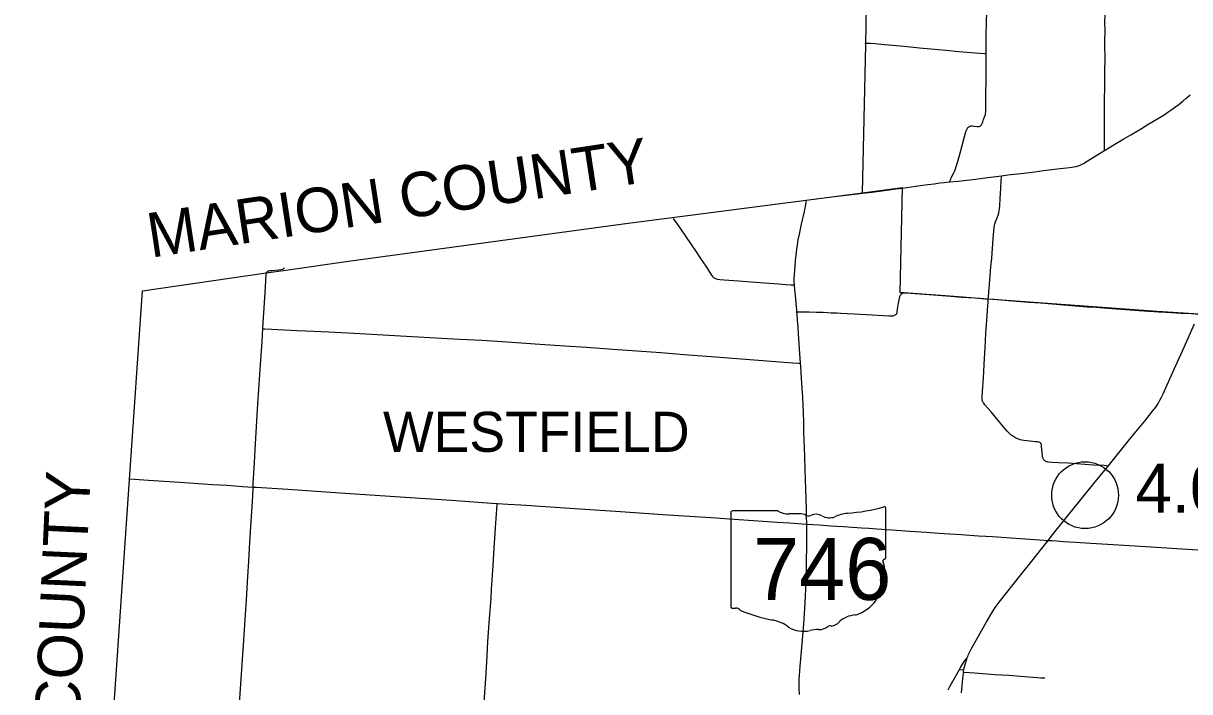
# Model space of a CAD drawing. Extents: x 9078 to 9739, y 4248 to 4966.
# Drawn here: x 9110.2 to 9241.2, y 4481.6 to 4556.7 of the extents above; entities that cross this region are included whole.
import ezdxf

# ---------------------------------------------------------------- set-up
doc = ezdxf.new("R2010")
doc.units = 0
for name, color, linetype in [('Default', 7, 'Continuous'), ('GM_X_Adjacent_County_Text', 7, 'Continuous'), ('GM_X_County', 7, 'Continuous'), ('GM_X_County_Road', 7, 'Continuous'), ('GM_X_State_Route', 7, 'Continuous'), ('GM_X_State_Shield', 7, 'Continuous'), ('GM_X_Township', 7, 'Continuous'), ('GM_X_Township_Road', 7, 'Continuous'), ('GM_X_Township_Text', 7, 'Continuous'), ('GM_X_US_Route', 7, 'Continuous')]:
    doc.layers.add(name, color=color, linetype=linetype)

msp = doc.modelspace()

# ---------------------------------------------------------------- linework, layer by layer
at = {"layer": 'Default'}
msp.add_circle((9229.48, 4503.7), 3.75, dxfattribs=at)
at = {"layer": 'GM_X_County'}
msp.add_lwpolyline([(9120.12, 4475.84), (9122.16, 4505.46), (9123.61, 4526.66), (9137.52, 4528.67), (9139.7, 4528.98), (9147, 4530.03), (9178.15, 4534.24), (9183.12, 4534.88), (9198.17, 4536.84), (9204.48, 4537.65), (9204.85, 4554.27), (9205.29, 4580.7)], dxfattribs=at)
at = {"layer": 'GM_X_County_Road'}
for points in [[(9231.68, 4542.43), (9233.01, 4543.23), (9233.85, 4543.73), (9234.63, 4544.19), (9235.62, 4544.78), (9235.83, 4544.9), (9236.46, 4545.29), (9237.15, 4545.72), (9238.35, 4546.43), (9238.77, 4546.7), (9239.1, 4546.93), (9239.52, 4547.23), (9240, 4547.59), (9240.47, 4547.97), (9240.85, 4548.28), (9240.98, 4548.39), (9241.27, 4548.67)], [(9220.1, 4539.58), (9220.82, 4539.67), (9221.56, 4539.76), (9222.61, 4539.88), (9223.84, 4540.03), (9224.81, 4540.15), (9226.36, 4540.35), (9227.74, 4540.52), (9228.23, 4540.59), (9228.47, 4540.63), (9228.71, 4540.69), (9228.94, 4540.77), (9229.09, 4540.83), (9229.31, 4540.95), (9229.73, 4541.2), (9231.6, 4542.38), (9231.68, 4542.43)], [(9214.29, 4538.88), (9215.21, 4538.98), (9217.16, 4539.2), (9218.55, 4539.38), (9220.1, 4539.58)], [(9204.5, 4537.63), (9205.57, 4537.75), (9206.34, 4537.85)], [(9206.34, 4537.85), (9206.38, 4537.85), (9208.24, 4538.1), (9208.96, 4538.2)], [(9208.96, 4538.2), (9210.43, 4538.4), (9211.24, 4538.51), (9211.81, 4538.58), (9212.54, 4538.68), (9213.18, 4538.77), (9213.67, 4538.83), (9213.92, 4538.85), (9214.29, 4538.88)], [(9198.21, 4536.84), (9198.72, 4536.91), (9200.75, 4537.16), (9203.91, 4537.56), (9204.5, 4537.63)], [(9183.2, 4534.77), (9183.31, 4534.65), (9183.46, 4534.45), (9183.7, 4534.12), (9184.53, 4532.9), (9185.31, 4531.75), (9185.73, 4531.14), (9186.37, 4530.19), (9186.88, 4529.44), (9187.54, 4528.41), (9187.64, 4528.27), (9187.69, 4528.21), (9187.75, 4528.16), (9187.82, 4528.11), (9187.89, 4528.07), (9187.96, 4528.03), (9188.04, 4528.01), (9188.2, 4527.97), (9188.44, 4527.94), (9188.93, 4527.89), (9190.57, 4527.78), (9192.45, 4527.63), (9194, 4527.52), (9195.06, 4527.43), (9195.88, 4527.37), (9196.45, 4527.32), (9196.69, 4527.31), (9196.83, 4527.31)], [(9137.14, 4522.41), (9137.18, 4523.07), (9137.39, 4526.43), (9137.51, 4528.49), (9137.52, 4528.58), (9137.53, 4528.65)], [(9137.53, 4528.65), (9137.54, 4528.71), (9137.57, 4528.76), (9137.6, 4528.8), (9137.64, 4528.83), (9137.69, 4528.86), (9137.76, 4528.89), (9137.84, 4528.91), (9137.94, 4528.93), (9138.17, 4528.95), (9138.9, 4529.02), (9139.14, 4529.05), (9139.3, 4529.08), (9139.38, 4529.1), (9139.45, 4529.13), (9139.5, 4529.17), (9139.55, 4529.22)], [(9197.12, 4524.28), (9197.22, 4524.29), (9197.37, 4524.3), (9197.53, 4524.31), (9197.86, 4524.3), (9198.51, 4524.29), (9199.33, 4524.27), (9200.07, 4524.24), (9200.97, 4524.2), (9201.63, 4524.18), (9202.04, 4524.16), (9202.78, 4524.12), (9203.6, 4524.06), (9205.56, 4523.94), (9206.79, 4523.87), (9207.45, 4523.83), (9207.69, 4523.83), (9207.86, 4523.85), (9207.94, 4523.86), (9208.01, 4523.88), (9208.09, 4523.92), (9208.16, 4523.95), (9208.23, 4524), (9208.3, 4524.05), (9208.34, 4524.11), (9208.37, 4524.17), (9208.38, 4524.27), (9208.43, 4524.6), (9208.53, 4525.25), (9208.62, 4525.81), (9208.66, 4525.97), (9208.69, 4526.05), (9208.69, 4526.05)], [(9208.69, 4526.05), (9208.72, 4526.12), (9208.77, 4526.19), (9208.82, 4526.25), (9208.88, 4526.31), (9208.95, 4526.35), (9209.02, 4526.39), (9209.1, 4526.41), (9209.18, 4526.43), (9209.34, 4526.43), (9209.92, 4526.39), (9210.9, 4526.31), (9211.96, 4526.23), (9214.42, 4526.05), (9215.65, 4525.96), (9217.12, 4525.85), (9218.27, 4525.77), (9218.61, 4525.75)], [(9218.61, 4525.75), (9219.25, 4525.7), (9220.88, 4525.57), (9223.18, 4525.39), (9224.48, 4525.29), (9227.1, 4525.08), (9229.72, 4524.87), (9230.7, 4524.8), (9231.6, 4524.73), (9232.5, 4524.67), (9234.55, 4524.53), (9235.53, 4524.46), (9236.59, 4524.38), (9237.25, 4524.35), (9237.74, 4524.31), (9238.56, 4524.24), (9239.77, 4524.18), (9240.23, 4524.15), (9240.85, 4524.13), (9241.43, 4524.11), (9241.84, 4524.08), (9242.16, 4524.05), (9242.27, 4524.03)], [(9136.04, 4504.61), (9136.05, 4504.64), (9136.06, 4505.05), (9136.18, 4507.35), (9136.26, 4508.82), (9136.57, 4513.98), (9136.9, 4518.89), (9137.04, 4520.94), (9137.14, 4522.41)], [(9122.18, 4505.54), (9124.29, 4505.38), (9127.81, 4505.16), (9131.49, 4504.92), (9133.13, 4504.81), (9134.84, 4504.69), (9136.04, 4504.61)], [(9134.13, 4474.93), (9134.14, 4475.01), (9134.26, 4476.72), (9134.53, 4480.82), (9134.76, 4484.17), (9134.95, 4486.87), (9135.17, 4490.31), (9135.28, 4491.95), (9135.41, 4493.92), (9135.45, 4494.57), (9135.55, 4496.29), (9135.67, 4498.42), (9135.82, 4500.71), (9136, 4503.58), (9136.04, 4504.61)], [(9136.04, 4504.61), (9136.4, 4504.59), (9139.92, 4504.36), (9145.81, 4503.96), (9153.67, 4503.44), (9157.19, 4503.2), (9158.82, 4503.09), (9162.83, 4502.82), (9163.47, 4502.78)], [(9163.47, 4502.78), (9164.63, 4502.7), (9166.11, 4502.6), (9173.31, 4502.14), (9177.32, 4501.88), (9182.07, 4501.55), (9188.04, 4501.15), (9189.51, 4501.06), (9191.15, 4500.94), (9194.91, 4500.68), (9196.3, 4500.59), (9198.1, 4500.46), (9198.23, 4500.45)], [(9215.37, 4484.12), (9215.5, 4484.34), (9215.96, 4485.12), (9216.02, 4485.21), (9216.1, 4485.29), (9216.23, 4485.42)], [(9214.09, 4481.84), (9214.33, 4482.28), (9215.37, 4484.12)], [(9215.37, 4484.12), (9215.45, 4484.11), (9215.77, 4484.08), (9215.86, 4484.07)]]:
    msp.add_lwpolyline(points, dxfattribs=at)
at = {"layer": 'GM_X_State_Route'}
msp.add_lwpolyline([(9197.4, 4481.31), (9197.37, 4482.05), (9197.36, 4482.62), (9197.36, 4483.03), (9197.39, 4483.44), (9197.47, 4484.5), (9197.59, 4485.73), (9197.71, 4487.04), (9197.82, 4488.34), (9197.89, 4489.24), (9197.99, 4490.96), (9198.08, 4492.35), (9198.12, 4493.17), (9198.18, 4494.48), (9198.2, 4495.46), (9198.21, 4496.53), (9198.22, 4497.76), (9198.23, 4499.4), (9198.23, 4500.38), (9198.23, 4500.45), (9198.21, 4501.36), (9198.19, 4502.18), (9198.15, 4503.33), (9198.12, 4504.4), (9198.09, 4505.46), (9198.05, 4506.53), (9198, 4508.08), (9197.97, 4508.98), (9197.91, 4510.79), (9197.88, 4511.85), (9197.85, 4513), (9197.77, 4514.72), (9197.71, 4515.7), (9197.63, 4516.85), (9197.54, 4518.16), (9197.52, 4518.53), (9197.41, 4520.12), (9197.29, 4521.84), (9197.24, 4522.57), (9197.19, 4523.31), (9197.14, 4524.04), (9197.12, 4524.28), (9197.1, 4524.53), (9197.04, 4525.19), (9196.98, 4525.76), (9196.87, 4526.82), (9196.83, 4527.31), (9196.83, 4527.35), (9196.82, 4527.64), (9196.82, 4528.05), (9196.84, 4528.46), (9196.87, 4528.95), (9196.97, 4530.01), (9197.1, 4531.32), (9197.17, 4531.81), (9197.26, 4532.37), (9197.39, 4533.02), (9197.63, 4534.14), (9197.95, 4535.58), (9198.14, 4536.54), (9198.21, 4536.84)], dxfattribs=at)
at = {"layer": 'GM_X_State_Shield'}
for p, q in [((9189.7, 4501.76), (9189.7, 4491.19)), ((9194.97, 4501.94), (9189.87, 4501.94)), ((9207.1, 4496.68), (9207.1, 4502.2)), ((9207.1, 4496.68), (9207.1, 4496.68))]:
    msp.add_line(p, q, dxfattribs=at)
for centre, major_axis, start_param, end_param in [((9189.9, 4501.78), (0.202, 0), 1.712693, 3.28349), ((9196.18, 4503.17), (1.96, 0), 4.042523, 4.731795), ((9196.83, 4496.01), (7.02, 0), 1.404758, 1.657858), ((9198.42, 4501.84), (0.564, 0), 3.836095, 5.185415), ((9199.25, 4500.62), (1.17, 0), 0.950623, 2.079405), ((9200.77, 4502.29), (1.41, 0), 4.081561, 5.145723), ((9203.26, 4498.71), (3.71, 0), 1.699011, 2.107814), ((9200.9, 4516.35), (18.45, 0), 4.814394, 5.042369), ((9206.91, 4502.23), (0.194, 0), 6.141152, 7.989035), ((9207.06, 4496.27), (0.3, 0), 1.883978, 3.671073), ((9205.15, 4495.57), (1.8, 0), 5.934695, 6.695948), ((9206.9, 4496.66), (0.207, 0), 5.05454, 6.418171), ((9207.8, 4494.36), (1.31, 0), 2.387724, 3.262537), ((9201.94, 4493.66), (4.62, 0), 5.101752, 6.440018), ((9189.9, 4491.17), (0.203, 0), 3.00124, 4.508301), ((9189.93, 4492.25), (1.55, 0), 4.665946, 4.897461), ((9190.25, 4490.58), (0.56, 0), 0.519207, 1.627899), ((9197.32, 4500.08), (13.33, 0), 4.195997, 4.488961), ((9193.34, 4486.45), (4.17, 0), 0.823519, 1.323587), ((9200.68, 4490.17), (1.49, 0), 4.937069, 5.64225), ((9203.88, 4488.23), (2.53, 0), 1.647645, 2.488434), ((9197.85, 4490.53), (2.65, 0), 4.026481, 4.996735), ((9199.38, 4486.88), (2.17, 0), 1.495662, 1.94098), ((9199.57, 4489.74), (1.41, 0), 4.691044, 5.507374), ((9200.85, 4488.72), (0.397, 0), 1.147584, 2.315152)]:
    msp.add_ellipse(centre, major_axis=major_axis, ratio=0.8, start_param=start_param, end_param=end_param, dxfattribs=at)
at = {"layer": 'GM_X_Township'}
msp.add_lwpolyline([(9204.48, 4537.65), (9208.95, 4538.24), (9208.67, 4526.47), (9209.13, 4526.47), (9213.78, 4526.12), (9218.61, 4525.77), (9237.59, 4524.37), (9242.26, 4524.06), (9243.8, 4523.9), (9245.68, 4523.76), (9281.77, 4520.95)], dxfattribs=at)
at = {"layer": 'GM_X_Township_Road'}
for points in [[(9218.36, 4553.27), (9218.36, 4553.33), (9218.37, 4554.15), (9218.39, 4555.29), (9218.41, 4556.85), (9218.44, 4557.92), (9218.47, 4558.98), (9218.49, 4559.8), (9218.5, 4560.01)], [(9231.68, 4542.43), (9231.67, 4542.85), (9231.66, 4544.32), (9231.66, 4545.38), (9231.66, 4546.04), (9231.68, 4548.5), (9231.69, 4549.07), (9231.71, 4550.96), (9231.72, 4553.09), (9231.71, 4554), (9231.71, 4554.65), (9231.72, 4555.88), (9231.71, 4556.79), (9231.72, 4557.61), (9231.74, 4559.25), (9231.75, 4559.92)], [(9204.74, 4554.45), (9205.38, 4554.46), (9205.9, 4554.42), (9206.96, 4554.33), (9209.18, 4554.12), (9210.9, 4553.96), (9213.03, 4553.76), (9213.85, 4553.69), (9215.32, 4553.55), (9217.12, 4553.38), (9218.19, 4553.29), (9218.36, 4553.27)], [(9214.29, 4538.88), (9214.34, 4539.03), (9214.39, 4539.18), (9214.45, 4539.33), (9214.74, 4539.92), (9214.84, 4540.14), (9214.94, 4540.37), (9215.02, 4540.6), (9215.16, 4541.07), (9215.38, 4541.86), (9215.63, 4542.81), (9215.86, 4543.69), (9216.05, 4544.4), (9216.09, 4544.56), (9216.15, 4544.71), (9216.19, 4544.79), (9216.23, 4544.86), (9216.27, 4544.93), (9216.32, 4544.99), (9216.38, 4545.04), (9216.45, 4545.09), (9216.52, 4545.13), (9216.6, 4545.15), (9216.68, 4545.17), (9216.76, 4545.18), (9216.84, 4545.18), (9217.01, 4545.16), (9217.33, 4545.12), (9217.42, 4545.11), (9217.5, 4545.11), (9217.58, 4545.12), (9217.66, 4545.15), (9217.73, 4545.18), (9217.79, 4545.23), (9217.85, 4545.29), (9217.89, 4545.36), (9217.93, 4545.43), (9217.98, 4545.59), (9218.09, 4545.9), (9218.2, 4546.21), (9218.28, 4546.44), (9218.31, 4546.6), (9218.33, 4546.77), (9218.34, 4547.18), (9218.35, 4547.75), (9218.35, 4548.49), (9218.36, 4550.62), (9218.36, 4551.6), (9218.36, 4552.26), (9218.36, 4553.27)], [(9218.61, 4525.75), (9218.63, 4525.91), (9218.63, 4525.99), (9218.79, 4527.87), (9218.91, 4529.35), (9218.99, 4530.33), (9219.16, 4532.54), (9219.22, 4533.35), (9219.26, 4533.76), (9219.3, 4534.01), (9219.34, 4534.16), (9219.42, 4534.4), (9219.6, 4534.86), (9219.71, 4535.16), (9219.79, 4535.4), (9219.84, 4535.64), (9219.87, 4535.88), (9219.9, 4536.21), (9219.95, 4537.03), (9220.02, 4538.16), (9220.07, 4539.03), (9220.09, 4539.43), (9220.1, 4539.58)], [(9218.1, 4514.03), (9218.08, 4514.06), (9218.03, 4514.13), (9217.99, 4514.2), (9217.96, 4514.27), (9217.94, 4514.35), (9217.92, 4514.43), (9217.92, 4514.51), (9217.92, 4514.6), (9217.93, 4514.84), (9217.99, 4515.83), (9218.06, 4516.89), (9218.19, 4519.1), (9218.25, 4520.25), (9218.35, 4521.89), (9218.48, 4523.86), (9218.56, 4525), (9218.58, 4525.3), (9218.61, 4525.75)], [(9137.14, 4522.41), (9137.28, 4522.4), (9137.37, 4522.39), (9139.58, 4522.28), (9140.97, 4522.21), (9142.86, 4522.11), (9144.5, 4522.03), (9146.71, 4521.92), (9148.68, 4521.82), (9153.26, 4521.56), (9157.2, 4521.35), (9159.25, 4521.24), (9161.71, 4521.1), (9164.57, 4520.93), (9168.26, 4520.68), (9171.04, 4520.49), (9173.5, 4520.32), (9176.44, 4520.1), (9181.85, 4519.71), (9184.47, 4519.51), (9185.94, 4519.4), (9188.48, 4519.21), (9190.36, 4519.06), (9196.66, 4518.58), (9197.31, 4518.54), (9197.52, 4518.53)], [(9232.07, 4506.96), (9231.88, 4506.99), (9231.8, 4507.01), (9231.64, 4507.02), (9230.41, 4507.09), (9229.02, 4507.18), (9227.54, 4507.28), (9226.48, 4507.34), (9225.74, 4507.38), (9225.33, 4507.42), (9225.25, 4507.43), (9225.17, 4507.45), (9225.09, 4507.48), (9225.02, 4507.52), (9224.95, 4507.57), (9224.89, 4507.62), (9224.84, 4507.68), (9224.8, 4507.75), (9224.76, 4507.83), (9224.74, 4507.91), (9224.71, 4508.07), (9224.62, 4508.88), (9224.6, 4509.12), (9224.58, 4509.38), (9224.56, 4509.45), (9224.52, 4509.53), (9224.46, 4509.58), (9224.39, 4509.62), (9224.32, 4509.65), (9224.15, 4509.68), (9223.91, 4509.7), (9223.26, 4509.77), (9222.6, 4509.84), (9222.36, 4509.88), (9222.2, 4509.92), (9222.04, 4509.98), (9221.89, 4510.04), (9221.74, 4510.11), (9221.6, 4510.19), (9221.39, 4510.32), (9221.19, 4510.46), (9221.06, 4510.57), (9220.89, 4510.73), (9220.72, 4510.91), (9220.5, 4511.16), (9219.76, 4512.04), (9218.92, 4513.05), (9218.23, 4513.86), (9218.1, 4514.03)], [(9161.51, 4473.09), (9161.58, 4474.32), (9161.85, 4478.41), (9162.16, 4483.08), (9162.33, 4485.62), (9162.42, 4487.26), (9162.56, 4489.31), (9162.63, 4490.29), (9162.76, 4492.09), (9162.82, 4493.15), (9163, 4495.77), (9163.09, 4497.17), (9163.28, 4500.03), (9163.46, 4502.65), (9163.47, 4502.78)], [(9198.23, 4500.45), (9199.63, 4500.36), (9200.94, 4500.27), (9202.33, 4500.18), (9204.38, 4500.04), (9205.2, 4499.99), (9206.09, 4499.92), (9206.66, 4499.88)], [(9206.66, 4499.88), (9207.16, 4499.85), (9207.81, 4499.8), (9209.78, 4499.67), (9211.63, 4499.53), (9212.53, 4499.47), (9213.67, 4499.38), (9215.55, 4499.27), (9217.52, 4499.15), (9218.34, 4499.1), (9219.07, 4499.05), (9220.63, 4498.94), (9224.88, 4498.65), (9225.12, 4498.63), (9225.33, 4498.62)], [(9225.33, 4498.62), (9225.73, 4498.6), (9226.27, 4498.57), (9227.01, 4498.51), (9228.4, 4498.43), (9230.12, 4498.32), (9232.01, 4498.21), (9235.12, 4498.01), (9237.49, 4497.86), (9239.79, 4497.72), (9242.73, 4497.53), (9244.01, 4497.44)], [(9215.82, 4483.81), (9215.94, 4483.81), (9217.07, 4483.75), (9219.36, 4483.58), (9220.09, 4483.53), (9220.91, 4483.47), (9222.23, 4483.38), (9224.53, 4483.2), (9224.96, 4483.17)]]:
    msp.add_lwpolyline(points, dxfattribs=at)
at = {"layer": 'GM_X_US_Route'}
msp.add_lwpolyline([(9215.62, 4481.49), (9215.75, 4483.12), (9215.81, 4483.71), (9215.82, 4483.81), (9215.84, 4483.94), (9215.86, 4484.07), (9215.88, 4484.16), (9215.94, 4484.42), (9216.11, 4485.05), (9216.19, 4485.29), (9216.23, 4485.42), (9216.3, 4485.6), (9216.36, 4485.73), (9216.5, 4486.04), (9216.76, 4486.54), (9217.69, 4488.19), (9218.38, 4489.4), (9219.07, 4490.61), (9219.38, 4491.09), (9219.82, 4491.68), (9222.27, 4494.77), (9223.49, 4496.3), (9224.61, 4497.72), (9225.33, 4498.62), (9225.95, 4499.39), (9227.18, 4500.92), (9230.48, 4505), (9231.88, 4506.72), (9232.07, 4506.96), (9233.13, 4508.27), (9234.33, 4509.75), (9235, 4510.58), (9236.29, 4512.17), (9237.06, 4513.13), (9237.41, 4513.59), (9237.56, 4513.83), (9237.68, 4514), (9237.88, 4514.36), (9238.03, 4514.65), (9238.24, 4515.1), (9239.49, 4517.87), (9240.61, 4520.33), (9241.78, 4522.95)], dxfattribs=at)

# ---------------------------------------------------------------- texts
at = {"layer": 'Default'}
msp.add_text('4.00', height=5.5, dxfattribs=at).set_placement((9235.13, 4501.75))
at = {"layer": 'GM_X_Adjacent_County_Text'}
for rotation, p in [(8.6829, (9124.55, 4530.36)), (87.3751, (9115.2, 4449.51))]:
    msp.add_text('MARION COUNTY', height=5, rotation=rotation, dxfattribs=at).set_placement(p)
at = {"layer": 'GM_X_State_Shield'}
msp.add_text('746', height=6.961, dxfattribs=at).set_placement((9192.19, 4491.94))
at = {"layer": 'GM_X_Township_Text'}
msp.add_text('WESTFIELD', height=4.5, rotation=0, dxfattribs=at).set_placement((9150.63, 4508.57))

doc.saveas('drawing.dxf')
